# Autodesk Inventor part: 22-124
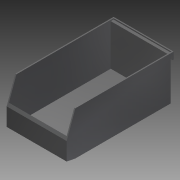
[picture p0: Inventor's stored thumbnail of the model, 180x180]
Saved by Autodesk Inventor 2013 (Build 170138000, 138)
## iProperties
Created: 2004-11
Part Number: 22-124
Document SubType Name: Modeling
Designer: Autodesk, Inc.
Manufacturer: Standard
Standards Organization: Custom
Vendor: PARKER IPS
Catalog Web Link: http://www.parker.com/ead/cm1.asp?cmid=809
Mass: 114.974 g
Surface Area: 1166.8 cm^2
Volume: 114.974 cm^3
Density: 1 g/cm^3
Description: Parts Bin, Conductive, Small
Material: Allgemein
CAGE: 1LJX3
Dept. ID: Product Design
Description #2: ---
Finish #1: ---
Finish #2: ---
Material ID: ---
Project Number: ---
Author: Autodesk, Inc.
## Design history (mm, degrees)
derived "22-1x Part Bins.ipt"
body "Solid1"
tag "TaggingFeature2"
feature "Solid1::22-1x Part Bins.ipt" dims "ScaleForDerivedMember" = 10
